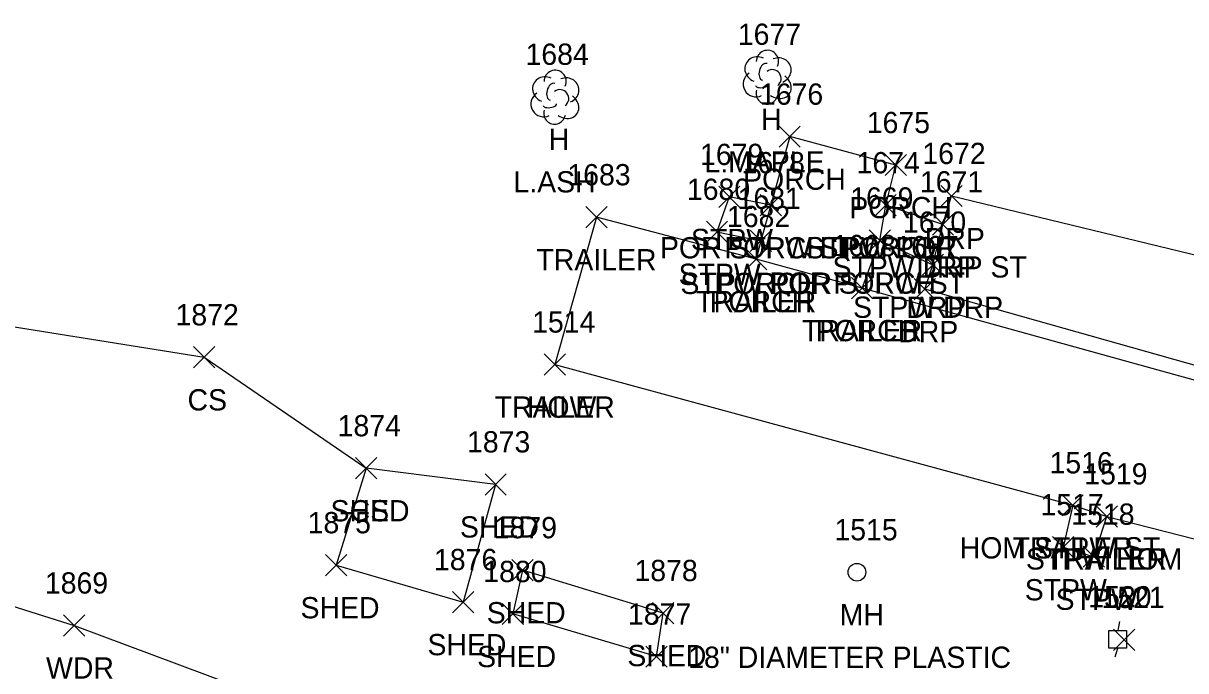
# Model space of a CAD drawing. Extents: x 1477930 to 1480780, y 774090 to 784647.
# Drawn here: x 1479170.3 to 1479279.7, y 774335.2 to 774396.1 of the extents above; entities that cross this region are included whole.
import ezdxf

# ---------------------------------------------------------------- set-up
doc = ezdxf.new("R2010")
doc.units = 0
for name, color, linetype in [('L_A', 7, 'Continuous'), ('L_C', 7, 'Continuous'), ('L_I', 7, 'Continuous'), ('L_TIC', 7, 'Continuous'), ('LAWA', 7, 'Continuous'), ('LBC', 7, 'Continuous'), ('LBF', 7, 'Continuous'), ('LELB', 7, 'Continuous'), ('LTD', 7, 'Continuous'), ('R_A', 7, 'Continuous'), ('R_I', 7, 'Continuous'), ('R_TIC', 7, 'Continuous'), ('RDP', 7, 'Continuous'), ('U_A', 7, 'Continuous'), ('U_C', 7, 'Continuous'), ('U_I', 7, 'Continuous'), ('U_TIC', 7, 'Continuous'), ('UEPT', 7, 'Continuous'), ('UUMH', 7, 'Continuous')]:
    doc.layers.add(name, color=color, linetype=linetype)

msp = doc.modelspace()

# ---------------------------------------------------------------- linework, layer by layer
at = {"layer": 'L_TIC'}
for points in [[(1479241.41, 774384.44), (1479243.41, 774386.44)], [(1479243.41, 774384.44), (1479241.41, 774386.44)], [(1479251.4, 774381.77), (1479253.4, 774383.77)], [(1479253.4, 774381.77), (1479251.4, 774383.77)], [(1479235.73, 774378.77), (1479237.73, 774380.77)], [(1479237.73, 774378.77), (1479235.73, 774380.77)], [(1479239.63, 774377.99), (1479241.63, 774379.99)], [(1479241.63, 774377.99), (1479239.63, 774379.99)], [(1479239.63, 774377.99), (1479241.63, 774379.99)], [(1479241.63, 774377.99), (1479239.63, 774379.99)], [(1479250.44, 774377.99), (1479252.44, 774379.99)], [(1479252.44, 774377.99), (1479250.44, 774379.99)], [(1479250.44, 774377.99), (1479252.44, 774379.99)], [(1479252.44, 774377.99), (1479250.44, 774379.99)], [(1479223.24, 774376.86), (1479225.24, 774378.86)], [(1479225.24, 774376.86), (1479223.24, 774378.86)], [(1479234.57, 774375.49), (1479236.57, 774377.49)], [(1479236.57, 774375.49), (1479234.57, 774377.49)], [(1479255.83, 774376.19), (1479257.83, 774378.19)], [(1479257.83, 774376.19), (1479255.83, 774378.19)], [(1479238.69, 774374.64), (1479240.69, 774376.64)], [(1479240.69, 774374.64), (1479238.69, 774376.64)], [(1479238.69, 774374.64), (1479240.69, 774376.64)], [(1479240.69, 774374.64), (1479238.69, 774376.64)], [(1479249.9, 774374.67), (1479251.9, 774376.67)], [(1479251.9, 774374.67), (1479249.9, 774376.67)], [(1479249.9, 774374.67), (1479251.9, 774376.67)], [(1479251.9, 774374.67), (1479249.9, 774376.67)], [(1479238.25, 774372.93), (1479240.25, 774374.93)], [(1479240.25, 774372.93), (1479238.25, 774374.93)], [(1479238.25, 774372.93), (1479240.25, 774374.93)], [(1479240.25, 774372.93), (1479238.25, 774374.93)], [(1479254.89, 774372.4), (1479256.89, 774374.4)], [(1479256.89, 774372.4), (1479254.89, 774374.4)], [(1479248.22, 774370.2), (1479250.22, 774372.2)], [(1479250.22, 774370.2), (1479248.22, 774372.2)], [(1479248.22, 774370.2), (1479250.22, 774372.2)], [(1479250.22, 774370.2), (1479248.22, 774372.2)], [(1479186.33, 774363.69), (1479188.33, 774365.69)], [(1479188.33, 774363.69), (1479186.33, 774365.69)], [(1479219.31, 774363.01), (1479221.31, 774365.01)], [(1479221.31, 774363.01), (1479219.31, 774365.01)], [(1479219.31, 774363.01), (1479221.31, 774365.01)], [(1479221.31, 774363.01), (1479219.31, 774365.01)], [(1479201.58, 774353.26), (1479203.58, 774355.26)], [(1479203.58, 774353.26), (1479201.58, 774355.26)], [(1479201.58, 774353.26), (1479203.58, 774355.26)], [(1479203.58, 774353.26), (1479201.58, 774355.26)], [(1479213.75, 774351.74), (1479215.75, 774353.74)], [(1479215.75, 774351.74), (1479213.75, 774353.74)], [(1479213.75, 774351.74), (1479215.75, 774353.74)], [(1479215.75, 774351.74), (1479213.75, 774353.74)], [(1479268.03, 774349.77), (1479270.03, 774351.77)], [(1479270.03, 774349.77), (1479268.03, 774351.77)], [(1479268.03, 774349.77), (1479270.03, 774351.77)], [(1479270.03, 774349.77), (1479268.03, 774351.77)], [(1479271.25, 774348.73), (1479273.25, 774350.73)], [(1479273.25, 774348.73), (1479271.25, 774350.73)], [(1479271.25, 774348.73), (1479273.25, 774350.73)], [(1479273.25, 774348.73), (1479271.25, 774350.73)], [(1479267.13, 774345.83), (1479269.13, 774347.83)], [(1479269.13, 774345.83), (1479267.13, 774347.83)], [(1479270.02, 774344.94), (1479272.02, 774346.94)], [(1479272.02, 774344.94), (1479270.02, 774346.94)], [(1479198.76, 774344.14), (1479200.76, 774346.14)], [(1479200.76, 774344.14), (1479198.76, 774346.14)], [(1479216.27, 774343.67), (1479218.27, 774345.67)], [(1479218.27, 774343.67), (1479216.27, 774345.67)], [(1479210.7, 774340.67), (1479212.7, 774342.67)], [(1479212.7, 774340.67), (1479210.7, 774342.67)], [(1479210.7, 774340.67), (1479212.7, 774342.67)], [(1479212.7, 774340.67), (1479210.7, 774342.67)], [(1479215.37, 774339.55), (1479217.37, 774341.55)], [(1479217.37, 774339.55), (1479215.37, 774341.55)], [(1479215.37, 774339.55), (1479217.37, 774341.55)], [(1479217.37, 774339.55), (1479215.37, 774341.55)], [(1479229.5, 774339.64), (1479231.5, 774341.64)], [(1479231.5, 774339.64), (1479229.5, 774341.64)], [(1479174.1, 774338.47), (1479176.1, 774340.47)], [(1479176.1, 774338.47), (1479174.1, 774340.47)], [(1479228.89, 774335.54), (1479230.89, 774337.54)], [(1479230.89, 774335.54), (1479228.89, 774337.54)], [(1479228.89, 774335.54), (1479230.89, 774337.54)], [(1479230.89, 774335.54), (1479228.89, 774337.54)]]:
    msp.add_lwpolyline(points, dxfattribs=at)
at = {"layer": 'LAWA'}
msp.add_lwpolyline([(1479132.45, 774321.38), (1479148.05, 774348), (1479175.1, 774339.47), (1479202.22, 774329.33)], dxfattribs=at)
at = {"layer": 'LBC'}
for points in [[(1479220.31, 774364.01), (1479269.03, 774350.77), (1479272.25, 774349.73), (1479290.03, 774345.16), (1479293.95, 774358.81), (1479249.22, 774371.2), (1479239.25, 774373.93), (1479224.24, 774377.86)], [(1479224.24, 774377.86), (1479220.31, 774364.01)], [(1479214.75, 774352.74), (1479202.58, 774354.26), (1479199.76, 774345.14), (1479211.7, 774341.67)], [(1479214.75, 774352.74), (1479211.7, 774341.67)], [(1479229.89, 774336.54), (1479230.5, 774340.64), (1479217.27, 774344.67), (1479216.37, 774340.55)], [(1479229.89, 774336.54), (1479216.37, 774340.55)]]:
    msp.add_lwpolyline(points, dxfattribs=at)
at = {"layer": 'LBF'}
for points in [[(1479249.22, 774371.2), (1479250.9, 774375.67), (1479251.44, 774378.99), (1479252.4, 774382.77), (1479242.41, 774385.44), (1479240.63, 774378.99), (1479239.69, 774375.64), (1479239.25, 774373.93)], [(1479240.63, 774378.99), (1479236.73, 774379.77), (1479235.57, 774376.49), (1479239.69, 774375.64)], [(1479250.9, 774375.67), (1479255.89, 774373.4), (1479256.83, 774377.19), (1479251.44, 774378.99)], [(1479269.03, 774350.77), (1479268.13, 774346.83), (1479271.02, 774345.94), (1479272.25, 774349.73)]]:
    msp.add_lwpolyline(points, dxfattribs=at)
at = {"layer": 'LELB'}
msp.add_lwpolyline([(1479112.17, 774335.82), (1479123.22, 774351.66), (1479162.97, 774368.59), (1479187.33, 774364.69), (1479202.58, 774354.26)], dxfattribs=at)
at = {"layer": 'LTD'}
for p, q in [((1479240.27, 774391.07), (1479240.27, 774391.07)), ((1479240.27, 774391.07), (1479240.27, 774391.07)), ((1479220.3, 774389.19), (1479220.3, 774389.19)), ((1479220.3, 774389.19), (1479220.3, 774389.19))]:
    msp.add_line(p, q, dxfattribs=at)
for centre in [(1479240.32, 774392.51), (1479220.35, 774390.63)]:
    msp.add_arc(centre, 1.05, 335.5272, 180.9563, dxfattribs=at)
for centre, major_axis, ratio, start_param, end_param in [((1479239.48, 774391.74), (1.21, -0.51), 0.895232, 1.570796, 4.712389), ((1479241.32, 774391.66), (-1.14, -0.48), 0.949671, 1.570796, 4.712389), ((1479240.07, 774391.53), (-0.208, -0.792), 0.645439, 3.141593, 6.283185), ((1479240.78, 774390.91), (-0.5, 0.667), 0.989748, 3.141593, 6.283185), ((1479219.51, 774389.86), (1.21, -0.51), 0.895232, 1.570796, 4.712389), ((1479220.1, 774389.65), (-0.208, -0.792), 0.645439, 3.141593, 6.283185), ((1479221.35, 774389.78), (-1.14, -0.48), 0.949671, 1.570796, 4.712389), ((1479239.19, 774390.36), (0.58, -1.04), 0.959034, 3.141593, 6.283185), ((1479239.82, 774390.32), (-0.625, -0.083), 0.423636, 0, 3.141593), ((1479241.28, 774390.24), (-1.09, 0.79), 0.841452, 1.570796, 4.712389), ((1479219.22, 774388.48), (0.58, -1.04), 0.959034, 3.141593, 6.283185), ((1479220.8, 774389.03), (-0.5, 0.667), 0.989748, 3.141593, 6.283185), ((1479221.3, 774388.36), (-1.09, 0.79), 0.841452, 1.570796, 4.712389), ((1479240.28, 774389.57), (0.26, 1.06), 0.942809, 1.570796, 4.712389), ((1479219.85, 774388.44), (-0.625, -0.083), 0.423636, 0, 3.141593), ((1479220.31, 774387.69), (0.26, 1.06), 0.942809, 1.570796, 4.712389)]:
    msp.add_ellipse(centre, major_axis=major_axis, ratio=ratio, start_param=start_param, end_param=end_param, dxfattribs=at)
at = {"layer": 'R_TIC'}
for points in [[(1479256.63, 774378.86), (1479258.63, 774380.86)], [(1479258.63, 774378.86), (1479256.63, 774380.86)], [(1479255.83, 774376.19), (1479257.83, 774378.19)], [(1479257.83, 774376.19), (1479255.83, 774378.19)], [(1479254.89, 774372.4), (1479256.89, 774374.4)], [(1479256.89, 774372.4), (1479254.89, 774374.4)], [(1479254.13, 774370.1), (1479256.13, 774372.1)], [(1479256.13, 774370.1), (1479254.13, 774372.1)], [(1479254.13, 774370.1), (1479256.13, 774372.1)], [(1479256.13, 774370.1), (1479254.13, 774372.1)]]:
    msp.add_lwpolyline(points, dxfattribs=at)
at = {"layer": 'RDP'}
for points in [[(1479256.83, 774377.19), (1479257.63, 774379.86), (1479283.25, 774373.67)], [(1479255.13, 774371.1), (1479255.89, 774373.4)], [(1479324.18, 774341.9), (1479321.03, 774345.9), (1479296.49, 774351.57), (1479298.11, 774358.95), (1479255.13, 774371.1)]]:
    msp.add_lwpolyline(points, dxfattribs=at)
at = {"layer": 'U_TIC'}
for points in [[(1479272.87, 774337.11), (1479274.87, 774339.11)], [(1479274.87, 774337.11), (1479272.87, 774339.11)]]:
    msp.add_lwpolyline(points, dxfattribs=at)
at = {"layer": 'UEPT'}
for p, q in [((1479272.43, 774337.34), (1479272.43, 774339.01)), ((1479272.43, 774339.01), (1479274.1, 774339.01)), ((1479273.43, 774339.84), (1479273.27, 774339.01)), ((1479274.1, 774339.01), (1479274.1, 774337.34)), ((1479273.27, 774338.17), (1479273.27, 774338.17)), ((1479274.1, 774337.34), (1479272.43, 774337.34)), ((1479273.02, 774336.51), (1479273.27, 774337.34))]:
    msp.add_line(p, q, dxfattribs=at)
at = {"layer": 'UUMH'}
for p, q in [((1479248.74, 774344.48), (1479248.74, 774344.48)), ((1479249.58, 774344.48), (1479249.58, 774344.48))]:
    msp.add_line(p, q, dxfattribs=at)
msp.add_circle((1479248.74, 774344.48), 0.833, dxfattribs=at)

# ---------------------------------------------------------------- texts
at = {"layer": 'L_A'}
for s, p in [('H', (1479239.71, 774386.07)), ('H', (1479219.74, 774384.19)), ('PORCH', (1479238.03, 774380.44)), ('PORCH', (1479248.02, 774377.77)), ('STPW', (1479233.12, 774374.77)), ('POR STPW ST', (1479230.21, 774373.99)), ('PORCH', (1479236.25, 774373.99)), ('STPW POR', (1479243.88, 774373.99)), ('PORCH', (1479247.06, 774373.99)), ('TRAILER', (1479218.59, 774372.86)), ('STPW DRP ST', (1479246.44, 774372.19)), ('STPW', (1479231.96, 774371.49)), ('STPW POR', (1479232.13, 774370.64)), ('PORCH', (1479235.31, 774370.64)), ('POR STPW ST', (1479240.48, 774370.67)), ('PORCH', (1479246.52, 774370.67)), ('TRAILER', (1479233.61, 774368.93)), ('PORCH', (1479234.87, 774368.93)), ('STPW DRP', (1479248.37, 774368.4)), ('TRAILER', (1479243.57, 774366.2)), ('PORCH', (1479244.84, 774366.2)), ('CS', (1479185.77, 774359.69)), ('TRAILER', (1479214.66, 774359.01)), ('HOW', (1479217.69, 774359.01)), ('SHED', (1479199.22, 774349.26)), ('CS', (1479201.02, 774349.26)), ('SHED', (1479211.39, 774347.74)), ('SHED', (1479211.39, 774347.74)), ('HOM STPW ST', (1479258.41, 774345.77)), ('TRAILER', (1479263.39, 774345.77)), ('STPW HOM', (1479264.63, 774344.73)), ('TRAILER', (1479266.6, 774344.73)), ('STPW', (1479264.52, 774341.83)), ('STPW', (1479267.42, 774340.94)), ('SHED', (1479196.4, 774340.14)), ('SHED', (1479213.91, 774339.67)), ('SHED', (1479208.34, 774336.67)), ('SHED', (1479208.34, 774336.67)), ('SHED', (1479213.01, 774335.55)), ('SHED', (1479213.01, 774335.55)), ('SHED', (1479227.14, 774335.64)), ('WDR', (1479172.46, 774334.47))]:
    msp.add_text(s, height=2, dxfattribs=at).set_placement(p)
at = {"layer": 'L_C'}
for s, p in [('L.MAPLE', (1479234.39, 774382.07)), ('L.ASH', (1479216.43, 774380.19))]:
    msp.add_text(s, height=2, dxfattribs=at).set_placement(p)
at = {"layer": 'L_I'}
for s, p in [('1677', (1479237.53, 774394.07)), ('1684', (1479217.56, 774392.19)), ('1676', (1479239.61, 774388.44)), ('1675', (1479249.66, 774385.77)), ('1679', (1479233.98, 774382.77)), ('1678', (1479237.89, 774381.99)), ('1678', (1479237.89, 774381.99)), ('1674', (1479248.7, 774381.99)), ('1674', (1479248.7, 774381.99)), ('1683', (1479221.5, 774380.86)), ('1671', (1479254.66, 774380.19)), ('1680', (1479232.74, 774379.49)), ('1681', (1479237.51, 774378.64)), ('1681', (1479237.51, 774378.64)), ('1669', (1479248.1, 774378.67)), ('1669', (1479248.1, 774378.67)), ('1682', (1479236.51, 774376.93)), ('1682', (1479236.51, 774376.93)), ('1670', (1479253.06, 774376.4)), ('1668', (1479246.43, 774374.2)), ('1668', (1479246.43, 774374.2)), ('1872', (1479184.64, 774367.69)), ('1514', (1479218.18, 774367.01)), ('1514', (1479218.18, 774367.01)), ('1874', (1479199.89, 774357.26)), ('1874', (1479199.89, 774357.26)), ('1873', (1479212.06, 774355.74)), ('1873', (1479212.06, 774355.74)), ('1516', (1479266.85, 774353.77)), ('1516', (1479266.85, 774353.77)), ('1519', (1479270.12, 774352.73)), ('1519', (1479270.12, 774352.73)), ('1517', (1479266, 774349.83)), ('1875', (1479197.07, 774348.14)), ('1518', (1479268.9, 774348.94)), ('1879', (1479214.57, 774347.67)), ('1876', (1479208.95, 774344.67)), ('1876', (1479208.95, 774344.67)), ('1880', (1479213.59, 774343.55)), ('1880', (1479213.59, 774343.55)), ('1878', (1479227.81, 774343.64)), ('1869', (1479172.35, 774342.47)), ('1877', (1479227.2, 774339.54)), ('1877', (1479227.2, 774339.54))]:
    msp.add_text(s, height=2, dxfattribs=at).set_placement(p)
at = {"layer": 'R_A'}
for p in [(1479255.12, 774374.86), (1479254.32, 774372.19), (1479253.38, 774368.4), (1479252.62, 774366.1), (1479252.62, 774366.1)]:
    msp.add_text('DRP', height=2, dxfattribs=at).set_placement(p)
at = {"layer": 'R_I'}
for s, p in [('1672', (1479254.89, 774382.86)), ('1671', (1479254.66, 774380.19)), ('1670', (1479253.06, 774376.4)), ('1667', (1479252.35, 774374.1)), ('1667', (1479252.35, 774374.1))]:
    msp.add_text(s, height=2, dxfattribs=at).set_placement(p)
at = {"layer": 'U_A'}
msp.add_text('MH', height=2, dxfattribs=at).set_placement((1479247.11, 774339.48))
at = {"layer": 'U_C'}
msp.add_text('18" DIAMETER PLASTIC', height=2, dxfattribs=at).set_placement((1479232.86, 774335.48))
at = {"layer": 'U_I'}
for s, p in [('1515', (1479246.62, 774347.48)), ('1520', (1479270.49, 774341.17)), ('1521', (1479271.74, 774341.11))]:
    msp.add_text(s, height=2, dxfattribs=at).set_placement(p)

doc.saveas('drawing.dxf')
